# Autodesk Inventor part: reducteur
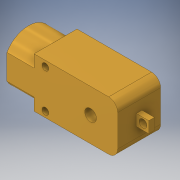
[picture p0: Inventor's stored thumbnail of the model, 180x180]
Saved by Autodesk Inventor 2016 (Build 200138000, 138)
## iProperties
Created: 2018-03
Part Number: reducteur
Material: Générique
Document SubType Name: Modeling
Designer: Bruno
Density: 1 g/cm^3
Appearance: Laiton - Satiné
Author: Bruno
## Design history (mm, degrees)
sketch "Esquisse1"
  geometry: L1 (0, 0)-(19, 0); L2 (19, 0)-(19, -22); L3 (19, -22)-(0, -22); L4 (0, -22)-(0, 0)
  constraints: 8 end point, 2 parallel, 1 horizontal, 1 perpendicular
  dimensions: "d0" = 19 distance of L2.end L3.end; "d1" = 22 distance of L1.end L2.end
extrude "Extrusion1" new body sketch "Esquisse1" distance "d2" = 37; taper "d3" = 0 deg
fillet "Congé2" dims "d5" = 4
sketch "Esquisse2"
  geometry: L1 (8.5, 8.25)-(13.5, 8.25); L2 (13.5, 8.25)-(13.5, 10.75); L3 (13.5, 10.75)-(8.5, 10.75); L4 (8.5, 10.75)-(8.5, 8.25); L5 (18, 19)-(4, 19) reference; L6 (4, 0)-(18, 0) reference; 1 further point
  constraints: 8 end point, 2 parallel, 1 horizontal, 1 perpendicular
  dimensions: "d6" = 2.5 distance of L3.end L1.start; "d7" = 5 distance of L2.end L3.end; "d9" = 8.25 distance between parallel lines of L6 L1; "d10" = 13.5 distance from line of point (0, 0) L2
extrude "Extrusion2" join sketch "Esquisse2" distance "d11" = 5.5; taper "d12" = 0 deg
sketch "Esquisse3"
  geometry: C1 r 1.75 at (2.961, 2.651); 1 further point
  constraints: 1 centre point
  dimensions: "d13" = 3.5 diameter of C1
extrude "Extrusion3" cut sketch "Esquisse3" distance "d14" = 5.5; taper "d15" = 0 deg
sketch "Esquisse4"
  geometry: L1 (0, 22)-(33, 22) reference; L2 (0, 0)-(0, 22) reference; L3 (0, 0)-(33, 0) reference; L4 (37, 18)-(37, 4) reference; L5 (25, 14.784)-(25, 7.237); L6 (37, 13.5)-(37, 8.5) reference; L7 (37, 11)-(21.931, 11); C1 r 2.6 at (25, 11); A1 r 4 centre (33, 18) between (37, 18) and (33, 22) reference; A2 r 4 centre (33, 4) between (33, 0) and (37, 4) reference; 1 further point
  constraints: 4 end point, 2 point on line, 1 centre point, 1 horizontal, 1 midpoint, 1 vertical
  dimensions: "d16" = 12 distance from line of L7.start L5; "d17" = 5.2 diameter of C1
extrude "Extrusion4" cut sketch "Esquisse4" distance "d18" = 5.5; taper "d19" = 0 deg
sketch "Esquisse5"
  geometry: C1 r 2.6 at (25, 11) reference; 1 further point
extrude "Extrusion5" cut sketch "Esquisse5" distance "d20" = 5.5; taper "d21" = 0 deg
sketch "Esquisse6"
  geometry: L1 (0, 0)-(0, 19) reference; L2 (0, 19)-(-22, 19) reference; L3 (-22, 19)-(-22, 0) reference; L4 (-22, 0)-(0, 0) reference; L5 (0, 19)-(-22, 19) reference; L6 (-5.455, 19)-(-6.672, 19); L7 (-4, 0)-(-18, 0) reference; L8 (-15.328, 19)-(-16.545, 19); L9 (-6.672, 19)-(-15.328, 19); L10 (-5.496, 0.629)-(-16.504, 0.629); L11 (-4, 0)-(-4, 19) reference; L12 (-5.496, 18.371)-(-16.504, 18.371); L13 (-5.455, 0)-(-16.545, 0); A1 r 11 centre (-11, 9.5) between (-16.545, 19) and (-16.545, 0); A2 r 11 centre (-11, 9.5) between (-5.455, 0) and (-5.455, 19); A3 r 10.439 centre (-11, 9.5) between (-5.496, 0.629) and (-5.496, 18.371); A4 r 10.439 centre (-11, 9.5) between (-16.504, 18.371) and (-16.504, 0.629); 1 further point
  constraints: 12 end point, 9 point on circle, 8 point on line, 4 centre point, 3 collinear, 1 coincident, 1 parallel, 1 perpendicular, 1 tangent
extrude "Extrusion6" join sketch "Esquisse6" distance "d22" = 12; taper "d23" = 0 deg
sketch "Esquisse7"
  geometry: L1 (0, 0)-(33, 0) reference; L2 (0, -5.455)-(0, 0) reference; L3 (0, -22)-(33, -22) reference; L4 (0, -22)-(0, -16.545) reference; C1 r 1.5 at (5, -2.5); C2 r 1.5 at (5, -19.5)
  constraints: 2 centre point
  dimensions: "d24" = 3 diameter of C1; "d25" = 2.5 distance from line of L1 C1.centre; "d26" = 5 distance from line of L2 C1.centre; "d29" = 3 diameter of C2; "d30" = 5 distance from line of L4 C2.centre; "d31" = 2.5 distance from line of L3 C2.centre
extrude "Extrusion7" cut sketch "Esquisse7" distance "d27" = 120; taper "d28" = 0 deg
node "Solide1"
node "Boucle projetée1"
node "Boucle projetée2"
